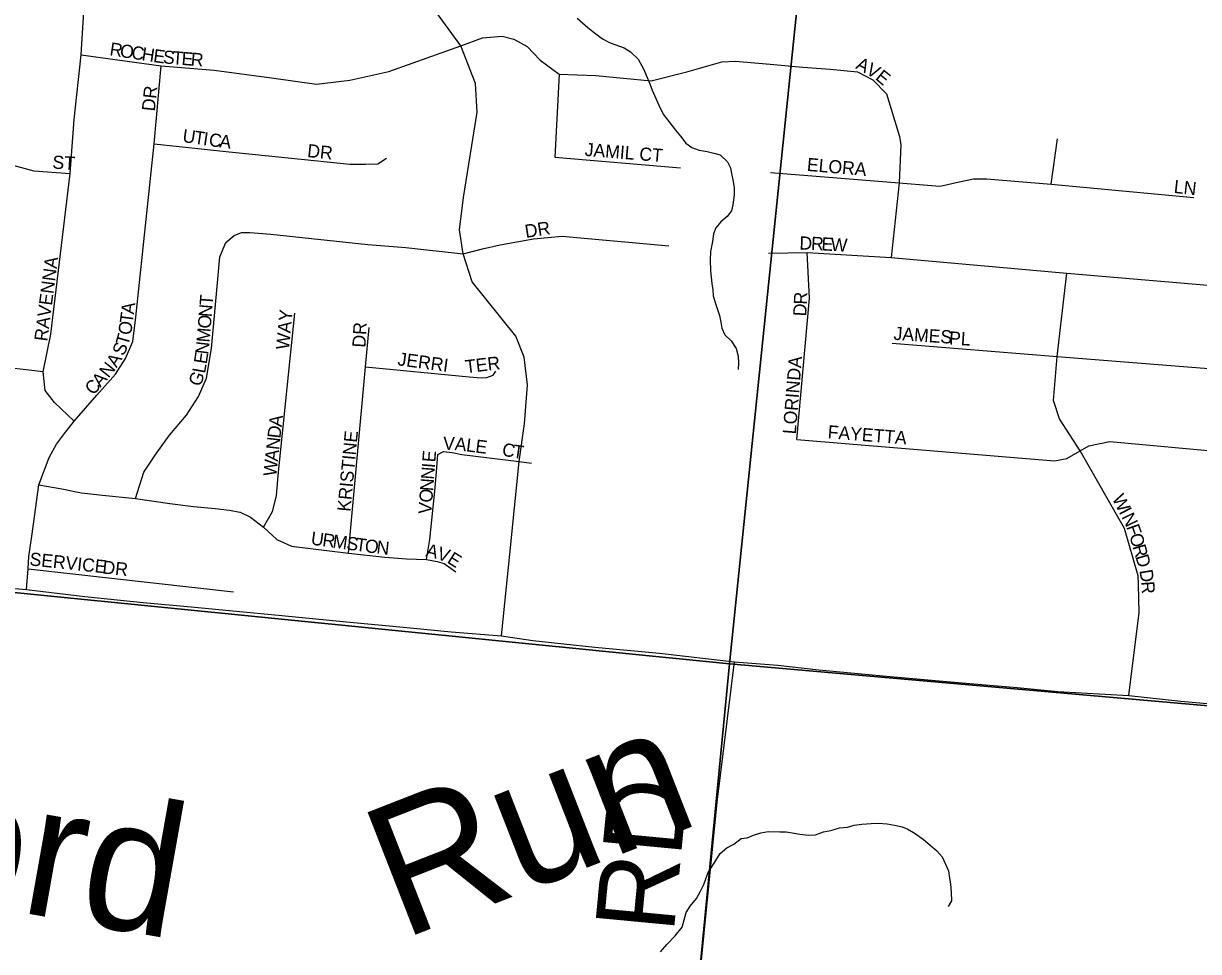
# Model space of a CAD drawing. Extents: x 1310247 to 1552180, y 377264 to 706493.
# Drawn here: x 1396444 to 1400913, y 511975 to 515505 of the extents above; entities that cross this region are included whole.
import ezdxf

# ---------------------------------------------------------------- set-up
doc = ezdxf.new("R2010")
doc.units = 0
for name, color, linetype in [('GM_X_Minor_River', 7, 'Continuous'), ('GM_X_Minor_River_Text', 7, 'Continuous'), ('GM_X_Section', 7, 'Continuous'), ('GM_X_Township_Road', 7, 'Continuous'), ('GM_X_Township_Road_Text', 7, 'Continuous'), ('GM_X_Township_Subdivision', 7, 'Continuous'), ('GM_X_Township_Subdivision_Text', 7, 'Continuous')]:
    doc.layers.add(name, color=color, linetype=linetype)

msp = doc.modelspace()

# ---------------------------------------------------------------- linework, layer by layer
at = {"layer": 'GM_X_Minor_River'}
for points in [[(1398549.1, 515524.6), (1398590.3, 515489.6), (1398615.9, 515468.9), (1398645.4, 515446.2), (1398675.1, 515431.4), (1398728.8, 515412), (1398752.5, 515397.4), (1398781.8, 515368.7), (1398802.9, 515330.1), (1398812.4, 515307.9), (1398825.7, 515275.6), (1398835.1, 515251.3), (1398850.3, 515216.9), (1398859.8, 515194.7), (1398877, 515160.2), (1398898.4, 515131.7), (1398923.6, 515099), (1398943.1, 515076.5), (1398962.5, 515050.1), (1398986.2, 515033.5), (1399014, 515022.8), (1399043.9, 515018), (1399069.8, 515011.3), (1399093.7, 515004.7), (1399121.1, 514978), (1399132.6, 514955.7), (1399136.1, 514933.6), (1399143.4, 514903.5), (1399146.8, 514879.4), (1399146.2, 514853.4), (1399141.3, 514815.5), (1399136.7, 514791.6), (1399120.2, 514770), (1399095.6, 514750.6), (1399077, 514727.1), (1399068.5, 514705.3), (1399063.8, 514675.5), (1399056.9, 514637.6), (1399056.1, 514605.6), (1399057.1, 514563.6), (1399061.9, 514515.5), (1399065.4, 514491.4), (1399066.8, 514469.3), (1399076.1, 514439.1), (1399091.1, 514394.7), (1399096.5, 514368.6), (1399099.9, 514346.5), (1399111.3, 514320.2), (1399134.9, 514297.6), (1399154.2, 514269.1), (1399161.5, 514238.9), (1399162.9, 514212.9)], [(1399162.9, 514212.9), (1399162.3, 514188.9)], [(1398866.5, 511974.1), (1398891.3, 512001.5), (1398922.1, 512034.7), (1398949, 512068.1), (1398964.3, 512123.7), (1398978.9, 512147.3), (1399003.7, 512176.7), (1399018.4, 512204.3), (1399031, 512230), (1399039.6, 512251.8), (1399048.1, 512275.6), (1399071.1, 512311), (1399094, 512348.4), (1399118.6, 512369.8), (1399144.9, 512383.1), (1399173.5, 512404.4), (1399195.6, 512407.8), (1399219.9, 512417.2), (1399248.2, 512426.5), (1399276.4, 512431.8), (1399320.4, 512430.7), (1399344.5, 512430.1), (1399374.4, 512425.3), (1399396.4, 512420.8), (1399430.4, 512417.9), (1399456.4, 512419.2), (1399486.8, 512430.5), (1399515, 512435.8), (1399547.2, 512444.9), (1399577.4, 512448.2), (1399603.6, 512455.5), (1399631.8, 512458.8), (1399667.9, 512461.9), (1399694, 512463.2), (1399728, 512460.3), (1399755.9, 512455.6), (1399785.8, 512448.9), (1399807.7, 512440.3), (1399835.3, 512423.6), (1399866.9, 512400.8), (1399890.4, 512380.2), (1399917.9, 512357.5), (1399937.4, 512335), (1399962.2, 512282.4), (1399965.5, 512254.3), (1399969, 512232.2), (1399972.3, 512200.1), (1399973.5, 512168.1), (1399960.9, 512146.4)]]:
    msp.add_lwpolyline(points, dxfattribs=at)
at = {"layer": 'GM_X_Section'}
for points in [[(1399715, 518763.5), (1399128.9, 513068.6), (1393469.6, 513633.9), (1394077.9, 519336.3)], [(1399715, 518763.5), (1405004.4, 518248.1), (1404461.2, 512601.7), (1399128.9, 513068.6)], [(1393469.6, 513633.9), (1399128.9, 513068.6), (1398704.7, 508684.1), (1398289.5, 508719.6), (1393070, 509536.8)], [(1399128.9, 513068.6), (1404461.2, 512601.7), (1404092.3, 509111.6), (1403401, 509422.4), (1398704.7, 508684.1)]]:
    msp.add_lwpolyline(points, close=True, dxfattribs=at)
at = {"layer": 'GM_X_Township_Road'}
for points in [[(1396172.8, 513375.4), (1396455.7, 513351.9), (1396677.5, 513325.2), (1396899.4, 513303), (1397081.7, 513286.6), (1397267.4, 513267.9), (1397426.3, 513252.7), (1397672.4, 513229.4), (1397875.7, 513210.3), (1398070.3, 513190.4), (1398262.4, 513175.7), (1398380.9, 513157.6), (1398616.3, 513132.5), (1398862.8, 513110), (1399147.5, 513077.1), (1399312.7, 513064.1), (1399468.5, 513046.8), (1399726.3, 513021.7), (1399998.8, 512998.4), (1400222.9, 512979.3), (1400377.7, 512964.6), (1400647.7, 512949), (1400844.9, 512926.6), (1401104.5, 512904.1)], [(1398951.4, 511217.4), (1398966.4, 511380.8), (1399082.2, 512543), (1399147.5, 513077.1)]]:
    msp.add_lwpolyline(points, dxfattribs=at)
at = {"layer": 'GM_X_Township_Subdivision'}
for points in [[(1396636.6, 513992.7), (1396562.3, 514063.3), (1396526.2, 514108.5), (1396519.1, 514179.5), (1396548.1, 514322.9), (1396622.2, 514934.3), (1396637.3, 515140), (1396663.1, 515385.2), (1396673, 515550.2), (1396692.8, 515673), (1396734.6, 516021.6), (1396937.7, 515993.7)], [(1398293.7, 513485.7), (1398329.5, 513839.1), (1398349.7, 513981.9), (1398361.4, 514130.4), (1398348.5, 514235.1), (1398316.4, 514314.9), (1398150, 514521.5), (1398115.6, 514629), (1398101.8, 514719.3), (1398117.3, 514843.3), (1398168.9, 515167.5), (1398162.5, 515276), (1398106.9, 515419.3), (1397980.8, 515593)], [(1396663.1, 515385.2), (1396967.8, 515344.2), (1397169.5, 515327.3), (1397386.7, 515297.7), (1397558.8, 515273.7), (1397685.7, 515289.2), (1397833.9, 515321.7), (1398106.9, 515419.3), (1398189.3, 515450), (1398264.8, 515456.4), (1398309.2, 515445.1), (1398359.2, 515417.6), (1398408.6, 515365.4), (1398480.9, 515312.5), (1398620.3, 515306.5), (1398831.4, 515286.6), (1398967.1, 515320.3), (1399099.9, 515358.8), (1399152.3, 515361.1), (1399283.4, 515350.3), (1399407.3, 515339), (1399512.4, 515330.4), (1399615.8, 515320.9), (1399673.7, 515290.6), (1399725.5, 515236.8), (1399775.6, 515074.3), (1399781.2, 515042.9), (1399774.3, 514898.8), (1399743.9, 514614.1)], [(1396455.7, 513351.9), (1396461.6, 513430.8), (1396464.3, 513477.3), (1396476.2, 513555.4), (1396486.6, 513636.9), (1396502.4, 513750.6), (1396541.9, 513853.8), (1396569.8, 513904.3), (1396600.5, 513945.8), (1396636.6, 513992.7), (1396723.2, 514091.1), (1396794.5, 514171.4), (1396832.4, 514231), (1396860.4, 514295), (1396871.2, 514388), (1396940.7, 515047.4), (1396967.8, 515344.2)], [(1398480.9, 515312.5), (1398465, 514995.8), (1398942.9, 514956)], [(1395826, 515046.2), (1395947.8, 515035.3), (1396164.2, 515011.5), (1396226.3, 515007.7), (1396307.3, 514997.7), (1396365, 514976.3), (1396483.6, 514943.7), (1396622.2, 514934.3)], [(1396940.7, 515047.4), (1397226.2, 515016.4), (1397463.4, 514992.3)], [(1400352.7, 514894.2), (1400376.6, 515065.5)], [(1397463.4, 514992.3), (1397684.6, 514969.9), (1397745.3, 514969.9), (1397791.8, 514971.2), (1397824.1, 514991.9)], [(1399285.4, 514938), (1399774.3, 514898.8), (1399896.9, 514889), (1399930.6, 514886.3), (1400002.3, 514902.2), (1400056.6, 514914.5), (1400105.8, 514914.2), (1400352.7, 514894.2), (1400894.4, 514842.4)], [(1396870.3, 513697.7), (1396901.9, 513798.7), (1396947.9, 513866.4), (1396999.4, 513938.6), (1397063.4, 514015.3), (1397109.5, 514085.7), (1397140.2, 514155.2), (1397159.1, 514268), (1397179, 514490.9), (1397190.7, 514617.2), (1397213.2, 514671.3), (1397244.8, 514698.4), (1397273.7, 514709.3), (1397304.4, 514709.3), (1397384.7, 514703.8), (1397753.8, 514664.1), (1397898.2, 514652.4), (1398115.6, 514629), (1398189.7, 514647.9), (1398256.4, 514662.3), (1398383.7, 514685.8), (1398492.9, 514695.7), (1398898.9, 514659.6)], [(1399277.5, 514631.3), (1399424.5, 514633.9), (1399743.9, 514614.1), (1400412.5, 514555.6), (1401201, 514487.9), (1401539.6, 514456)], [(1399385, 513922.2), (1399432.8, 514460), (1399424.5, 514633.9)], [(1400684.3, 513369.2), (1400683.3, 513404.4), (1400631.5, 513583.6), (1400462.6, 513879.2), (1400384.4, 514001.5), (1400361.1, 514071.4), (1400375.2, 514238.7), (1400412.5, 514555.6)], [(1397356.7, 513589.4), (1397391, 513648), (1397406.4, 513708.5), (1397412.7, 513785.2), (1397475.8, 514403.3)], [(1397680.7, 513490.7), (1397745.1, 514199.1), (1397758.8, 514348.9)], [(1399747.4, 514288.7), (1400375.2, 514238.7), (1401495.7, 514149.3)], [(1396519.1, 514179.5), (1396320.8, 514202.8)], [(1397745.1, 514199.1), (1398139.5, 514161.3), (1398185.1, 514157.5), (1398206.6, 514158.7), (1398229.7, 514167.6), (1398240.1, 514182.6)], [(1399385, 513922.2), (1400364.6, 513840.8), (1400412.5, 513850.5), (1400462.6, 513879.2), (1400496.1, 513898.3), (1400575.8, 513914.3), (1401017.8, 513874.4), (1401459.9, 513826.6)], [(1397976.7, 513465.7), (1397989.9, 513541.7), (1398009.6, 513738.9), (1398015.4, 513816.1), (1398019.5, 513866), (1398041.5, 513876.3), (1398074.3, 513872.8), (1398111.1, 513865.1), (1398329.5, 513839.1), (1398375.7, 513832.8)], [(1396502.4, 513750.6), (1396589.7, 513734.6), (1396664.6, 513720.2), (1396744.9, 513710.3), (1396870.3, 513697.7), (1397001.2, 513678.7), (1397090.5, 513667.9), (1397173.6, 513659.7), (1397227.7, 513654.3), (1397266.5, 513646.2), (1397267.7, 513645.7)], [(1397267.7, 513645.7), (1397308, 513627.3), (1397356.7, 513589.4), (1397407.3, 513541.5), (1397463.2, 513517.2), (1397680.7, 513490.7), (1397817.9, 513474.8), (1397900.9, 513468.4), (1397976.7, 513465.7), (1398017.3, 513458.5), (1398044.4, 513450.4), (1398087.7, 513418.8)], [(1398262.4, 513175.7), (1398293.7, 513485.7)], [(1396461.6, 513430.8), (1397242.8, 513343.4)], [(1400647.7, 512949), (1400687.3, 513265), (1400684.3, 513369.2)]]:
    msp.add_lwpolyline(points, dxfattribs=at)

# ---------------------------------------------------------------- texts
at = {"layer": 'GM_X_Minor_River_Text'}
for s, rotation, p in [('Crawford', 349.9055, (1394336.6, 512497.1)), ('Run', 21.3415, (1397883.6, 512019))]:
    msp.add_text(s, height=499.99, rotation=rotation, dxfattribs=at).set_placement(p)
at = {"layer": 'GM_X_Township_Road_Text'}
msp.add_text('RD', height=300, rotation=84.5832, dxfattribs=at).set_placement((1398916.5, 512042))
at = {"layer": 'GM_X_Township_Subdivision_Text'}
for s, rotation, p in [('R', 351.1984, (1396769.4, 515384.2)), ('O', 351.1791, (1396808.6, 515378.1)), ('C', 351.1863, (1396852, 515371.4)), ('H', 351.1791, (1396891.2, 515365.3)), ('E', 352.1872, (1396935.6, 515358.4)), ('S', 354.8778, (1396973, 515353.3)), ('T', 355.4622, (1397008.6, 515350.2)), ('E', 355.4869, (1397043.7, 515347.4)), ('R', 355.4853, (1397078.8, 515344.6)), ('A', 333.1466, (1399605.7, 515334.9)), ('V', 329.7373, (1399644.3, 515315.4)), ('E', 320.4953, (1399680.5, 515294.5)), ('DR', 83.9889, (1396943.4, 515169.1)), ('U', 351.7308, (1397046.6, 515054.2)), ('T', 351.7212, (1397090.1, 515047.9)), ('I', 351.7461, (1397125, 515042.8)), ('C', 351.7136, (1397146.7, 515039.6)), ('A', 352.6496, (1397186.8, 515033.8)), ('DR', 353.9946, (1397521.4, 514997)), ('JAMIL CT', 355.3918, (1398577.1, 515001.4)), ('ST', 356.4258, (1396553, 514953.1)), ('ELORA', 355.0282, (1399422, 514944.3)), ('LN', 353.6631, (1400817, 514860.6)), ('DR', 8.9829, (1398354.7, 514688.9)), ('D', 358.7323, (1399394.5, 514645.1)), ('R', 356.9872, (1399438.1, 514644.1)), ('E', 356.6376, (1399477.5, 514642)), ('W', 356.6355, (1399512.7, 514640)), ('RAVENNA', 82.5696, (1396534.3, 514294)), ('T', 85.5383, (1397163.1, 514430.7)), ('R', 87.7333, (1399423.2, 514434.9)), ('A', 82.7005, (1396863.7, 514397)), ('N', 85.5141, (1397159.6, 514386.8)), ('WAY', 84.6433, (1397453.8, 514262.6)), ('D', 86.6432, (1399420.6, 514389.9)), ('O', 81.9024, (1396853, 514317.8)), ('T', 82.7051, (1396859.3, 514362.1)), ('O', 85.517, (1397156.2, 514342.9)), ('T', 73.9355, (1396841.6, 514276.5)), ('M', 85.469, (1397152, 514290.3)), ('DR', 86.8215, (1397744.2, 514271)), ('JAMES', 356.0968, (1399751.8, 514301.9)), ('PL', 356.4258, (1399963, 514284.3)), ('S', 66.4835, (1396825.2, 514237.6)), ('N', 83.0562, (1397146.4, 514244.3)), ('A', 57.8939, (1396798, 514193)), ('E', 81.0502, (1397140.7, 514207.6)), ('JERRI', 352.3083, (1397864.8, 514205)), ('TER', 6.8478, (1398126.5, 514174.2)), ('LORINDA', 85.3901, (1399381, 513941.2)), ('N', 51.6355, (1396767.2, 514153.7)), ('L', 79.8996, (1397134.4, 514171.9)), ('C', 47.4478, (1396708.9, 514088.3)), ('A', 48.8608, (1396736.6, 514118.5)), ('G', 69.2418, (1397116.1, 514121)), ('A', 83.5391, (1397425.9, 513968.7)), ('D', 83.5536, (1397421, 513924.9)), ('FAYETTA', 355.4647, (1399501.1, 513927.2)), ('N', 83.5484, (1397416, 513881.2)), ('KRISTINE', 84.559, (1397687, 513646.6)), ('V', 357.9671, (1398039.1, 513883.9)), ('A', 353.7141, (1398082.1, 513882.4)), ('L', 352.8784, (1398125.6, 513877.6)), ('A', 83.5391, (1397411.1, 513837.5)), ('E', 85.6216, (1398010.1, 513834.6)), ('E', 352.8647, (1398160.6, 513873.2)), ('C', 349.6952, (1398261.4, 513861.7)), ('T', 351.5981, (1398302.1, 513854.3)), ('W', 84.189, (1397405.3, 513780.7)), ('N', 85.6123, (1398005.1, 513768.8)), ('I', 85.603, (1398008.4, 513812.7)), ('N', 85.603, (1398001.7, 513724.9)), ('O', 85.6139, (1397998.3, 513681)), ('W', 297.3471, (1400582.3, 513698.4)), ('V', 85.613, (1397995, 513637.2)), ('I', 297.3634, (1400608.6, 513647.6)), ('N', 296.0568, (1400618.6, 513628.4)), ('U', 352.2176, (1397534.9, 513523)), ('R', 352.2048, (1397578.5, 513517.1)), ('F', 289.096, (1400637.3, 513590.3)), ('M', 352.2196, (1397617.7, 513511.7)), ('S', 352.2176, (1397670.1, 513504.5)), ('T', 352.2041, (1397704.9, 513499.8)), ('O', 352.2194, (1397739.8, 513495)), ('N', 353.7626, (1397784.9, 513488.9)), ('A', 346.3428, (1397971.2, 513478.9)), ('O', 286.3747, (1400648.6, 513557.6)), ('R', 286.1956, (1400661, 513515.5)), ('SERVICE', 353.9906, (1396465.4, 513443.8)), ('V', 341.1953, (1398012.9, 513468.8)), ('E', 327.8976, (1398051.8, 513455.9)), ('D', 286.1811, (1400672, 513477.5)), ('DR', 353.9883, (1396742.6, 513413)), ('D', 279.1317, (1400687.6, 513424.1)), ('R', 273.6695, (1400694.5, 513381.9))]:
    msp.add_text(s, height=50, rotation=rotation, dxfattribs=at).set_placement(p)

doc.saveas('drawing.dxf')
